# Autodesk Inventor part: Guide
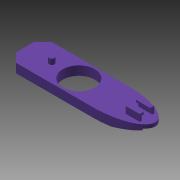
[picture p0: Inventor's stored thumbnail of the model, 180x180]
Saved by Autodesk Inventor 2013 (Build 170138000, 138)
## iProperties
Created: 2008-06
Part Number: Guide
Document SubType Name: Modeling
Designer: tangg
Density: 0.94 g/cm^3
Mass: 82.2056 g
Surface Area: 237.47 cm^2
Volume: 82.2056 cm^3
Stock Number: Guide
Material: UHMW, Black
Author: tangg
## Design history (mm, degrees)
sketch "Sketch1"
  geometry: L1 (107.721, 0)-(-76.2, 0); L2 (-76.2, 0)-(-76.2, -12.7); L3 (-76.2, -12.7)-(69.621, -12.7); L4 (107.721, -6.35)-(107.721, 0); L5 (107.721, -6.35)-(69.621, -12.7); 1 further point
  constraints: 10 end point, 1 point on line, 1 vertical
  dimensions: "d19" = 183.92109 distance of L1.start L1.end; "d20" = 76.2 distance from line of point (0, 0) L2; "d21" = 12.7 distance of L1.end L2.end; "d22" = 38.1 horizontal distance of L4.start L3.end
extrude "Extrusion2" new body sketch "Sketch1" distance "d2" = 25.4; taper "d3" = 0 deg
sketch "Sketch2"
  geometry: C1 r 22.5 at (76.2, 0); 1 further point
  constraints: 1 centre point, 1 coincident
  dimensions: "d25" = 45 diameter of C1
extrude "Extrusion3" cut sketch "Sketch2" stored distance "d4" = 12.7; taper "d5" = 0 deg
mirror "Mirror1"
sketch "Sketch4"
  geometry: L1 (-36.784, 25.4)-(220.705, 25.4) reference; C1 r 3.81 at (38.1, 25.4); 1 further point
  constraints: 1 centre point, 1 point on line
  dimensions: "d13" = 7.62 diameter of C1; "d39" = 38.1 distance of C1.centre point (76.2, 25.4)
extrude "Extrusion5" join sketch "Sketch4" distance "d8" = 7.62; taper "d9" = 0 deg
workplane "Work Plane1"
sketch "Sketch10"
  geometry: L1 (-69.621, 36.625)-(38.1, 36.625); L2 (-69.621, 14.175)-(38.1, 14.175); L3 (-69.621, 36.625)-(-69.621, 14.175); L4 (38.1, 0)-(38.1, 50.8) reference; L5 (38.1, 36.625)-(38.1, 14.175); A1 r 11.225 centre (-69.621, 25.4) between (-69.621, 36.625) and (-69.621, 14.175); 1 further point
  constraints: 8 end point, 4 point on circle, 3 point on line, 1 centre point, 1 horizontal
extrude "Extrusion11" cut sketch "Sketch10" stored distance "d32" = 15.24; taper "d33" = 0 deg
workplane "Work Plane4"
sketch "Sketch5"
  geometry: L1 (-1.587, -10.238)-(9.525, -10.238); L2 (9.525, -10.238)-(9.525, 10.238); L3 (9.525, 10.238)-(-1.588, 10.238); L4 (-1.588, 10.238)-(-1.587, -10.238); L5 (9.525, -7.62)-(0, -7.62); L6 (0, -7.62)-(0, 7.62); L7 (0, 7.62)-(9.525, 7.62); L8 (9.525, 7.62)-(9.525, -7.62); L9 (0, 25.4)-(0, -25.4) reference; L10 (9.525, -7.62)-(6.5, -7.62); L11 (6.5, -7.62)-(6.5, -4.62); L12 (6.5, -4.62)-(9.525, -4.62); L13 (9.525, -4.62)-(9.525, -7.62); L14 (9.525, 7.62)-(6.5, 7.62); L15 (6.5, 7.62)-(6.5, 4.62); L16 (6.5, 4.62)-(9.525, 4.62); L17 (9.525, 4.62)-(9.525, 7.62); 3 further points
  constraints: 32 end point, 3 midpoint, 1 collinear, 1 horizontal alignment, 1 point on line
  dimensions: "d14" = 15.24 distance between parallel lines of L7 L5; "d50" = 6.5 distance between parallel lines of L6 L11; "d51" = 3 distance between parallel lines of L10 L12; "d52" = 3 distance between parallel lines of L7 L16
extrude "Extrusion6" join sketch "Sketch5" distance "d11" = 20; taper "d12" = 0 deg
fillet "Fillet1" dims "d47" = 0.635
chamfer "Chamfer1" distance "d40" = 12.7; stored, may be unused: second distance "d41" = 3.175, angle "d42" = 45 deg
sketch "Sketch11"
  geometry: L1 (-5.08, 11.225)-(-12.7, 11.225) reference; L2 (-12.7, -11.225)-(-5.08, -11.225) reference; L3 (-12.7, 11.225)-(-6.35, 11.225) reference; L4 (-6.35, 11.225)-(-5.08, 11.225) reference; L5 (-5.08, 11.225)-(-5.08, -11.225) reference; L6 (-6.35, -11.225)-(-12.7, -11.225) reference; C1 r 2.54 at (-15.875, 0); A1 r 11.377 centre (-10.848, 0) between (-12.7, 11.225) and (-12.7, -11.225); 3 further points; 2 other entities
  constraints: 2 centre point, 2 point on circle, 2 other
  dimensions: "d48" = 3.175 distance of point (-12.7, 0) C1.centre; "d49" = 5.08 diameter of C1
extrude "Extrusion12" join sketch "Sketch11" stored distance "d37" = 12.7; taper "d38" = 0 deg
sketch "Sketch12"
  geometry: L1 (-171.221, 50.8)-(0, 50.8) reference; L2 (0, 0)-(0, 50.8) reference; L3 (-171.221, 0)-(0, 0) reference; L4 (0, 25.4)-(-107.721, 25.4); 3 further points; 1 other entity
  constraints: 3 point on line, 2 end point, 1 midpoint, 5 other
extrude "Extrusion13" cut sketch "Sketch12" stored distance "d43" = 25.4; taper "d44" = 0 deg
body "Solid1"
other parameters: "d10" = 76.2, "d34" = 63.5
